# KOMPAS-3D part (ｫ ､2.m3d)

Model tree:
1. Эскиз:1
2. Операция выдавливания:1
     Расстояние 1 = 52
3. Эскиз:2
4. Операция выдавливания:2
     Расстояние 1 = 8; Расстояние 2 = 8
5. Эскиз:3
6. Вырезать элемент выдавливания:1
     Расстояние 1 = 120
7. Эскиз:4
8. Вырезать элемент выдавливания:2
     Расстояние 1 = 120
9. Эскиз:5
10. Вырезать элемент выдавливания:3
     Расстояние 1 = 3; Угол 1 = 18
11. Эскиз:6
12. Вырезать элемент выдавливания:4
     Расстояние 1 = 2
